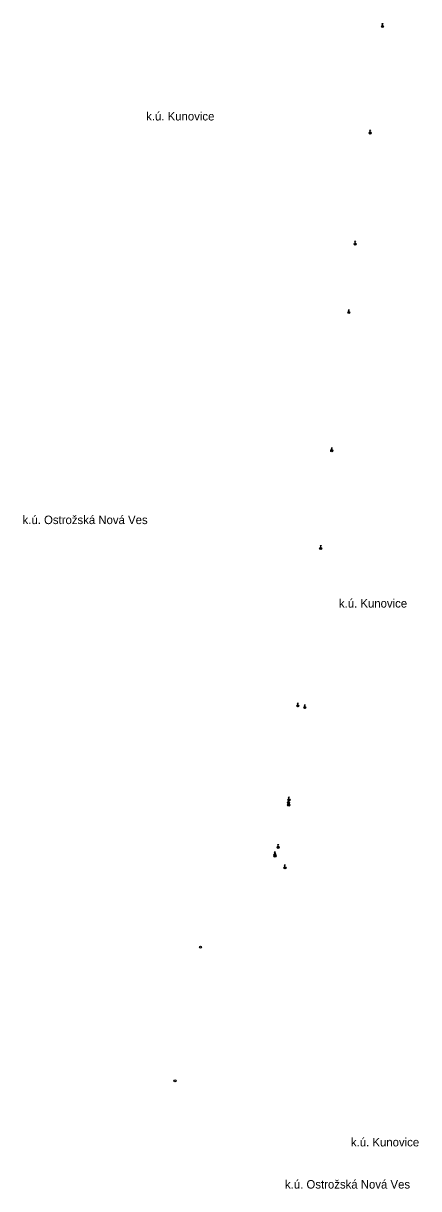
# Model space of a CAD drawing. Extents: x -540161 to -537510, y -1183993 to -1180459.
# Drawn here: x -540160.8 to -540021.3, y -1183992.8 to -1183581 of the extents above; entities that cross this region are included whole.
import ezdxf

# ---------------------------------------------------------------- set-up
doc = ezdxf.new("R2010")
doc.units = 0
for name, color, linetype in [('MAP_ZN_BP', 7, 'Continuous'), ('NÁZEV_K_Ú', 7, 'Continuous'), ('ZN_BP', 7, 'Continuous')]:
    doc.layers.add(name, color=color, linetype=linetype)

msp = doc.modelspace()

# ---------------------------------------------------------------- linework, layer by layer
at = {"layer": 'MAP_ZN_BP'}
for centre, radius in [((-540098.31, -1183907.421), 0.375), ((-540098.31, -1183907.421), 0.0005), ((-540107.33, -1183954.64), 0.375), ((-540107.33, -1183954.64), 0.0005)]:
    msp.add_circle(centre, radius, dxfattribs=at)
at = {"layer": 'ZN_BP'}
for p, q in [((-540034.365, -1183582.344), (-540033.836, -1183581.816)), ((-540033.836, -1183582.348), (-540034.365, -1183581.816)), ((-540034.1, -1183581.705), (-540034.1, -1183580.955)), ((-540038.705, -1183619.964), (-540038.176, -1183619.436)), ((-540038.176, -1183619.968), (-540038.705, -1183619.436)), ((-540038.44, -1183619.325), (-540038.44, -1183618.575)), ((-540043.7, -1183658.595), (-540043.7, -1183657.845)), ((-540043.965, -1183659.234), (-540043.436, -1183658.706)), ((-540043.436, -1183659.238), (-540043.965, -1183658.706)), ((-540046.235, -1183683.434), (-540045.706, -1183682.906)), ((-540045.706, -1183683.438), (-540046.235, -1183682.906)), ((-540045.97, -1183682.795), (-540045.97, -1183682.045)), ((-540052.255, -1183732.224), (-540051.726, -1183731.696)), ((-540051.726, -1183732.228), (-540052.255, -1183731.696)), ((-540051.99, -1183731.585), (-540051.99, -1183730.835)), ((-540055.89, -1183766.155), (-540055.89, -1183765.405)), ((-540056.155, -1183766.794), (-540055.626, -1183766.266)), ((-540055.626, -1183766.798), (-540056.155, -1183766.266)), ((-540064.215, -1183822.434), (-540063.686, -1183821.906)), ((-540063.686, -1183822.438), (-540064.215, -1183821.906)), ((-540063.95, -1183821.795), (-540063.95, -1183821.045)), ((-540061.735, -1183823.024), (-540061.206, -1183822.496)), ((-540061.206, -1183823.028), (-540061.735, -1183822.496)), ((-540061.47, -1183822.385), (-540061.47, -1183821.635)), ((-540067.495, -1183856.614), (-540066.966, -1183856.086)), ((-540066.966, -1183856.618), (-540067.495, -1183856.086)), ((-540067.345, -1183855.634), (-540066.816, -1183855.106)), ((-540066.816, -1183855.638), (-540067.345, -1183855.106)), ((-540067.23, -1183855.975), (-540067.23, -1183855.225)), ((-540067.18, -1183856.805), (-540067.18, -1183856.055)), ((-540067.08, -1183854.995), (-540067.08, -1183854.245)), ((-540067.445, -1183857.444), (-540066.916, -1183856.916)), ((-540066.916, -1183857.448), (-540067.445, -1183856.916)), ((-540071.145, -1183872.424), (-540070.616, -1183871.896)), ((-540070.616, -1183872.428), (-540071.145, -1183871.896)), ((-540070.88, -1183871.785), (-540070.88, -1183871.035)), ((-540072.335, -1183875.034), (-540071.806, -1183874.506)), ((-540071.806, -1183875.038), (-540072.335, -1183874.506)), ((-540072.275, -1183875.474), (-540071.746, -1183874.946)), ((-540071.746, -1183875.478), (-540072.275, -1183874.946)), ((-540072.07, -1183874.395), (-540072.07, -1183873.645)), ((-540072.01, -1183874.835), (-540072.01, -1183874.085)), ((-540068.775, -1183879.634), (-540068.246, -1183879.106)), ((-540068.246, -1183879.638), (-540068.775, -1183879.106)), ((-540068.51, -1183878.995), (-540068.51, -1183878.245))]:
    msp.add_line(p, q, dxfattribs=at)
for points in [[(-540034.225, -1183581.205), (-540034.1, -1183580.955), (-540033.975, -1183581.205)], [(-540038.565, -1183618.825), (-540038.44, -1183618.575), (-540038.315, -1183618.825)], [(-540043.825, -1183658.095), (-540043.7, -1183657.845), (-540043.575, -1183658.095)], [(-540046.095, -1183682.295), (-540045.97, -1183682.045), (-540045.845, -1183682.295)], [(-540052.115, -1183731.085), (-540051.99, -1183730.835), (-540051.865, -1183731.085)], [(-540056.015, -1183765.655), (-540055.89, -1183765.405), (-540055.765, -1183765.655)], [(-540064.075, -1183821.295), (-540063.95, -1183821.045), (-540063.825, -1183821.295)], [(-540061.595, -1183821.885), (-540061.47, -1183821.635), (-540061.345, -1183821.885)], [(-540067.355, -1183855.475), (-540067.23, -1183855.225), (-540067.105, -1183855.475)], [(-540067.305, -1183856.305), (-540067.18, -1183856.055), (-540067.055, -1183856.305)], [(-540067.205, -1183854.495), (-540067.08, -1183854.245), (-540066.955, -1183854.495)], [(-540071.005, -1183871.285), (-540070.88, -1183871.035), (-540070.755, -1183871.285)], [(-540072.195, -1183873.895), (-540072.07, -1183873.645), (-540071.945, -1183873.895)], [(-540072.135, -1183874.335), (-540072.01, -1183874.085), (-540071.885, -1183874.335)], [(-540068.635, -1183878.495), (-540068.51, -1183878.245), (-540068.385, -1183878.495)]]:
    msp.add_lwpolyline(points, dxfattribs=at)
for centre in [(-540034.1, -1183582.08), (-540038.44, -1183619.7), (-540043.7, -1183658.97), (-540045.97, -1183683.17), (-540051.99, -1183731.96), (-540055.89, -1183766.53), (-540063.95, -1183822.17), (-540061.47, -1183822.76), (-540067.23, -1183856.35), (-540067.08, -1183855.37), (-540067.18, -1183857.18), (-540070.88, -1183872.16), (-540072.07, -1183874.77), (-540072.01, -1183875.21), (-540068.51, -1183879.37)]:
    msp.add_circle(centre, 0.375, dxfattribs=at)

# ---------------------------------------------------------------- texts
at = {"layer": 'NÁZEV_K_Ú'}
for s, p in [('k.ú. Kunovice', (-540117.49, -1183615.29)), ('k.ú. Ostrožská Nová Ves', (-540161.12, -1183757.92)), ('k.ú. Kunovice', (-540049.458, -1183787.42)), ('k.ú. Kunovice', (-540045.218, -1183977.83)), ('k.ú. Ostrožská Nová Ves', (-540068.494, -1183992.73))]:
    msp.add_text(s, height=3, dxfattribs=at).set_placement(p)

doc.saveas('drawing.dxf')
